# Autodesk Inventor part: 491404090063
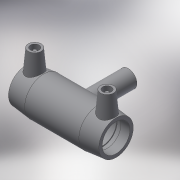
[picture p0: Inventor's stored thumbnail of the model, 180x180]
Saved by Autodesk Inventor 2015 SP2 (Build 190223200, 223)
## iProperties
Created: 2017-06
Part Number: 491404090063
Material: Generic
Description: PLASSON REDUCING TEE 90x63x90
Document SubType Name: Modeling
Designer: KIM
Mass: 57.3761 g
Surface Area: 241.06 cm^2
Volume: 57.3761 cm^3
Density: 1 g/cm^3
Appearance: Default
Author: KIM
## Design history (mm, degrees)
derived "491404.ipt"
feature "Solid1::491404.ipt"
tag "TaggingFeature1"
body "Solid1"
other parameters: "d0" = 294, "d2" = 113, "d3" = 68, "d4" = 58.8, "d5" = 101.7, "d6" = 85.5, "d8" = 168 deg, "d10" = 27.2, "d11" = 9.06667, "d13" = 294, "d14" = 17.6296, "d17" = 81, "d19" = 3.52592, "d20" = 168 deg, "d22" = 105.09, "d23" = 113, "d25" = 135 deg, "d26" = 205.8, "d29" = 71, "d30" = 15, "d31" = 117.6, "d34" = 5 deg, "d35" = 15, "d39" = 5 deg, "d41" = 4, "d42" = 14, "d43" = 0, "d45" = 4, "d46" = 6, "d47" = 0, "d48" = -124, "d49" = 63, "d51" = 0, "d52" = 50.4, "d54" = 0, "d55" = 101.7, "d56" = 113, "d57" = 102.9, "d58" = 135 deg, "d59" = 68, "d60" = 68, "d61" = 135 deg, "d62" = 124, "d72" = 133.77, "d73" = 66.885, "d74" = -124, "d75" = 66.15, "d77" = 0, "d78" = 50.4, "d80" = 0, "d81" = 63, "d82" = 67.5, "d83" = 0, "d84" = 3, "d85" = 0, "d86" = 22.66667, "d87" = 102.9882, "d88" = 9.06667, "d89" = 3, "d90" = 0, "L_" = 294, "L_1" = 68, "D_" = 113, "A_" = 71, "d_2" = 12, "H_" = 124, "d_1" = 63
